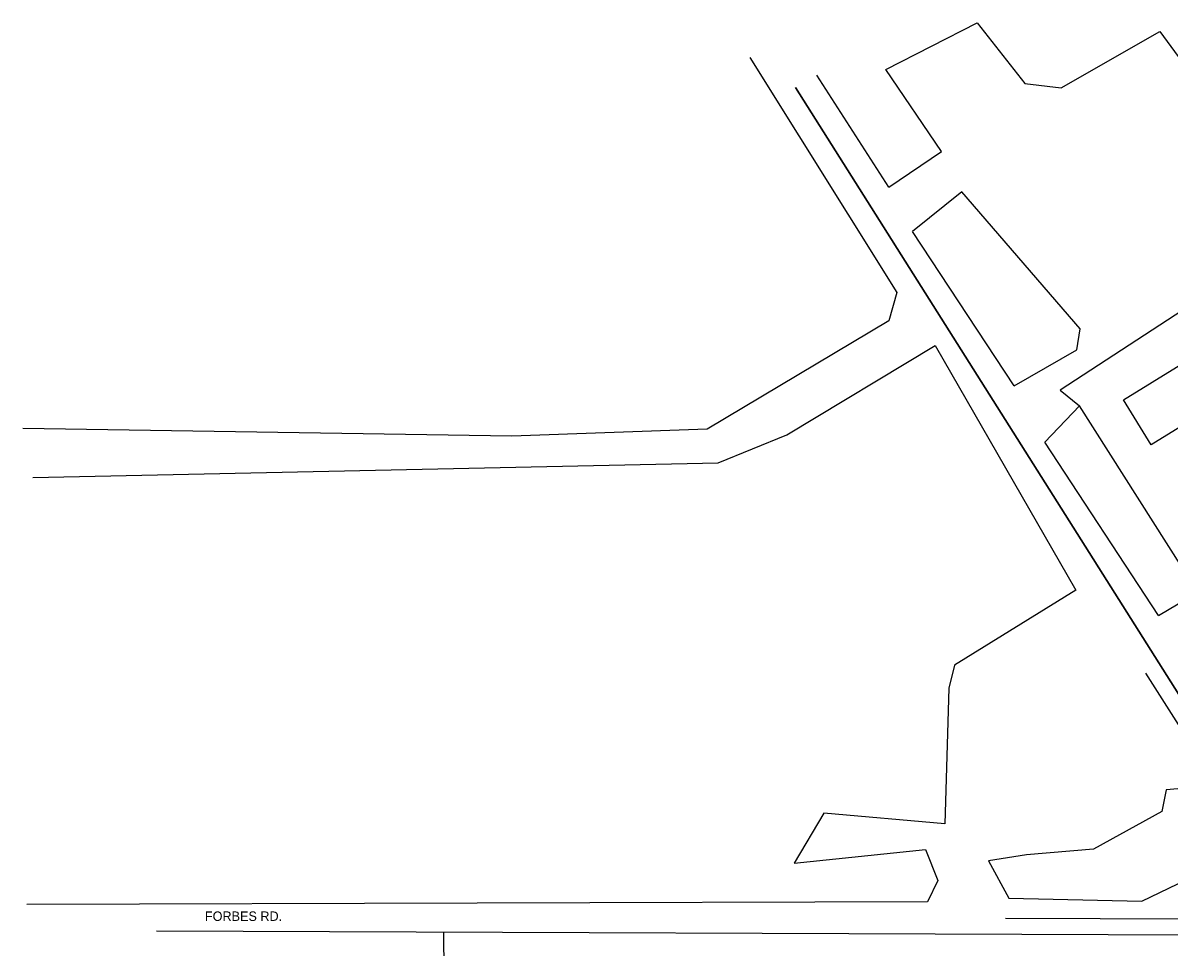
# Model space of a CAD drawing. Extents: x 227157 to 233208, y 434992 to 456232.
# Drawn here: x 227197 to 228046, y 445587 to 446272 of the extents above; entities that cross this region are included whole.
import ezdxf

# ---------------------------------------------------------------- set-up
doc = ezdxf.new("R2010")
doc.units = 0
for name, color, linetype in [('BD_X_Building', 7, 'Continuous'), ('GE_X_Alignment', 7, 'Continuous'), ('PM_X_Edge_Line', 7, 'Continuous'), ('PM_X_Lane_Line', 7, 'Continuous'), ('PV_X_EOP', 7, 'Continuous'), ('SV_X_Text_Name', 7, 'Continuous')]:
    doc.layers.add(name, color=color, linetype=linetype)

msp = doc.modelspace()

# ---------------------------------------------------------------- linework, layer by layer
at = {"layer": 'BD_X_Building'}
msp.add_lwpolyline([(228012.23, 445992.59), (228190.48, 446102.53), (228211.02, 446069.22), (228032.77, 445959.28)], close=True, dxfattribs=at)
at = {"layer": 'GE_X_Alignment'}
msp.add_line((227769.26, 446224.03), (229002.57, 444269.89), dxfattribs=at)
at = {"layer": 'PM_X_Edge_Line'}
for p, q in [((228568.1, 444958.3), (227769.26, 446224.03)), ((227295.85, 445599.2), (228101.26, 445595.88)), ((227518.85, 444557.09), (227508.75, 445598.33))]:
    msp.add_line(p, q, dxfattribs=at)
at = {"layer": 'PM_X_Lane_Line'}
for p, q in [((228323.43, 445323.49), (228028.93, 445790.11)), ((227924.77, 445608.61), (228114.81, 445607.83))]:
    msp.add_line(p, q, dxfattribs=at)
at = {"layer": 'PV_X_EOP'}
for p, q in [((227838.4, 446150.05), (227785.23, 446233.2)), ((227931.33, 446003.06), (227856.02, 446117.29)), ((228038.3, 445832.87), (227954.02, 445961.34))]:
    msp.add_line(p, q, dxfattribs=at)
for points in [[(227838.4, 446150.05), (227877.51, 446176.52), (227836.2, 446237.48), (227903.78, 446271.88), (227939.11, 446227.1), (227966.03, 446223.7), (228039.15, 446265.57), (228147.07, 446118.2), (227965.41, 445999.85), (227979.57, 445988.09)], [(227735.42, 446246.14), (227844.26, 446072.23), (227838.43, 446051.2), (227703.87, 445970.9), (227559.08, 445965.73), (227197.02, 445971.43)], [(227931.33, 446003.06), (227977.6, 446029.72), (227980.17, 446045.27), (227892.5, 446146.81), (227856.02, 446117.29)], [(227204.37, 445935.13), (227712.06, 445945.98), (227762.9, 445966.59), (227872.84, 446032.95), (227976.85, 445851.53), (227886.99, 445795.86), (227882.9, 445778.99), (227879.84, 445678.36), (227790.33, 445686.32), (227768.33, 445649.3), (227865.58, 445659.37), (227874.64, 445636.53), (227867.04, 445620.63), (227199.84, 445618.57)], [(228038.3, 445832.87), (228067.43, 445850.05), (227979.57, 445988.09), (227954.02, 445961.34)]]:
    msp.add_lwpolyline(points, dxfattribs=at)
msp.add_lwpolyline([(227927.3, 445623.39), (228025.8, 445621.2), (228072.47, 445643.54), (228077.52, 445683.23), (228061.25, 445705.16), (228043.97, 445703.57), (228040.66, 445687.56), (227990, 445659.58), (227940.36, 445655.34), (227912.15, 445650.96)], close=True, dxfattribs=at)

# ---------------------------------------------------------------- texts
at = {"layer": 'SV_X_Text_Name'}
msp.add_text('FORBES RD.', height=7, dxfattribs=at).set_placement((227331.84, 445606.47))

doc.saveas('drawing.dxf')
